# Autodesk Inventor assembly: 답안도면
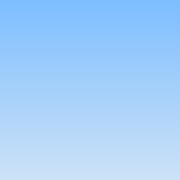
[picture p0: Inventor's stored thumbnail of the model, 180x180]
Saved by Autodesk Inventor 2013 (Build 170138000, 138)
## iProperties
Created: 2019-06
Part Number: 답안도면
Document SubType Name: Assembly
Designer: Administrator
Author: Administrator
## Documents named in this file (1)
- C:\Users\Administrator\Desktop\490604V1018\답안도면.iam
